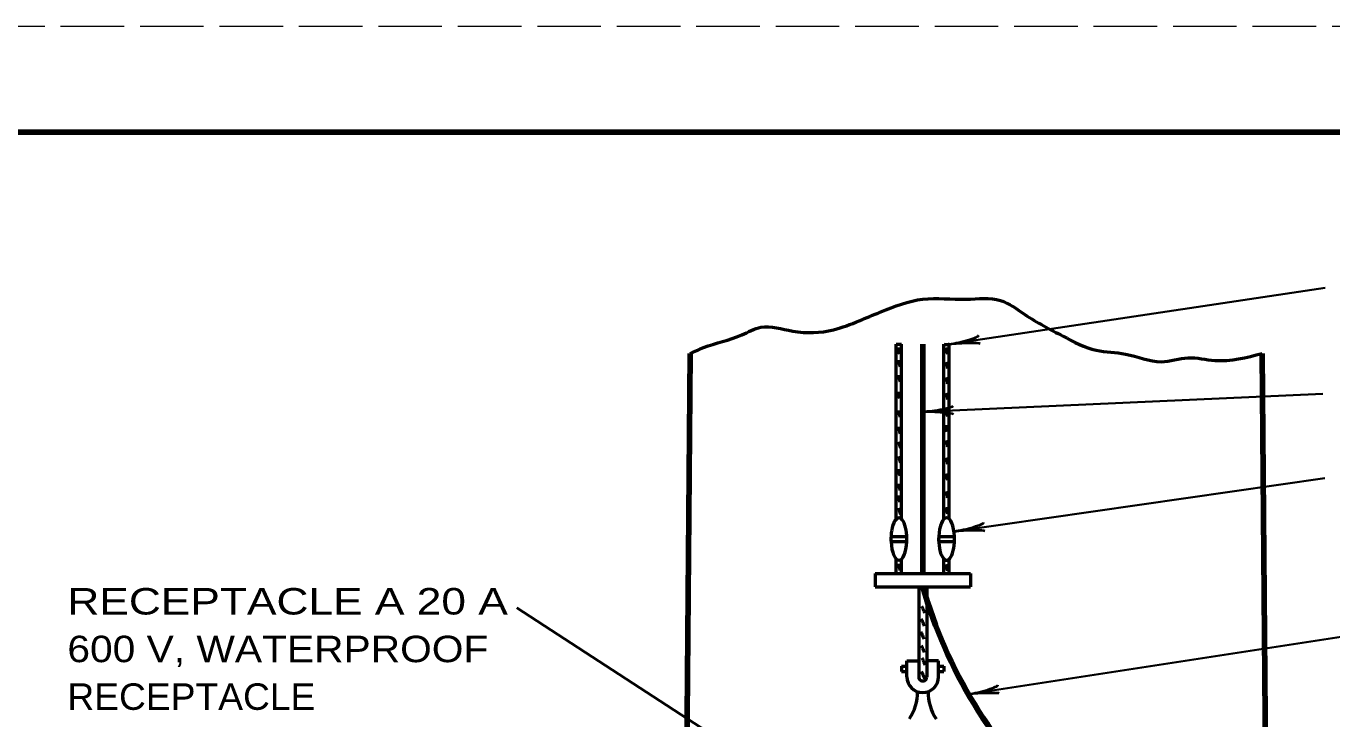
# Model space of a CAD drawing. Extents: x -1 to 679, y 0 to 440.
# Drawn here: x 332.8 to 456.1, y 374.2 to 439.6 of the extents above; entities that cross this region are included whole.
import ezdxf

# ---------------------------------------------------------------- set-up
doc = ezdxf.new("R2010")
doc.units = 0
doc.linetypes.add('LONG_DASHED', pattern=[7.5, 6, -1.5])
doc.layers.add('1', color=7, linetype='Continuous', lineweight=35)
doc.layers.add('61', color=7, linetype='Continuous', lineweight=35)

msp = doc.modelspace()

# ---------------------------------------------------------------- linework, layer by layer
at = {"layer": '1'}
for p, q in [((419.95, 409.606), (455.443, 414.94)), ((417.45, 403.246), (455.206, 404.943)), ((420.4, 391.942), (455.396, 396.984)), ((421.756, 376.569), (487.534, 386.706)), ((409.753, 364.833), (379.138, 384.739))]:
    msp.add_line(p, q, dxfattribs=at)
at = {"layer": '1', "lineweight": 53}
for p, q in [((414.95, 393.106), (414.95, 409.606)), ((415.45, 393.106), (415.45, 409.606)), ((419.45, 393.106), (419.45, 409.606)), ((419.95, 393.106), (419.95, 409.606)), ((414.456, 391.47), (415.944, 391.47)), ((415.944, 390.97), (414.456, 390.97)), ((418.956, 391.47), (420.444, 391.47)), ((420.444, 390.97), (418.956, 390.97)), ((414.95, 387.971), (414.95, 389.335)), ((415.45, 387.971), (415.45, 389.335)), ((419.45, 387.971), (419.45, 389.335)), ((419.95, 387.971), (419.95, 389.335)), ((412.95, 387.971), (421.95, 387.971)), ((412.95, 387.971), (412.95, 386.721)), ((421.95, 387.971), (421.95, 386.721)), ((412.95, 386.721), (421.95, 386.721)), ((417.075, 386.721), (417.075, 378.218)), ((417.825, 386.721), (417.825, 378.221)), ((415.95, 378.218), (415.95, 379.718)), ((415.95, 379.718), (417.075, 379.718)), ((418.95, 379.721), (417.825, 379.721)), ((418.95, 378.221), (418.95, 379.721)), ((415.45, 379.218), (415.95, 379.218)), ((415.45, 379.218), (415.45, 378.718)), ((415.45, 378.718), (415.95, 378.718)), ((418.95, 379.218), (419.45, 379.218)), ((418.95, 378.718), (419.45, 378.718)), ((419.45, 379.218), (419.45, 378.718))]:
    msp.add_line(p, q, dxfattribs=at)
at = {"layer": '1', "lineweight": 200}
msp.add_line((417.45, 387.971), (417.45, 409.606), dxfattribs=at)
at = {"layer": '1', "lineweight": 106}
for p, q in [((394.317, 267.245), (395.488, 408.744)), ((450.738, 257.745), (449.488, 408.744))]:
    msp.add_line(p, q, dxfattribs=at)
at = {"layer": '1', "lineweight": 200}
msp.add_arc((461.415, 399.379), 45.751, 196.06279, 226.51634, dxfattribs=at)
at = {"layer": '1', "lineweight": 53}
for centre, radius, start, end in [((417.45, 378.221), 1.5, 180.08989, 0), ((417.45, 378.197), 0.376, 176.82066, 3.53584), ((412.445, 376.744), 4.506, 326.28532, 0.79097), ((422.457, 376.744), 4.506, 179.20914, 213.71468)]:
    msp.add_arc(centre, radius, start, end, dxfattribs=at)
at = {"layer": '1', "lineweight": 40}
for centre, major_axis, ratio, start_param, end_param in [((420.988, 410.041), (-1.743, -0.42), 0.122415, 0.8963533, 3.1415927), ((420.988, 410.041), (-1.743, -0.42), 0.122415, 0.8963533, 3.1415927), ((421.09, 409.563), (1.763, 0.087), 0.07063, 6.2823074, 8.5597026), ((421.09, 409.563), (1.763, 0.087), 0.07063, 6.2823074, 8.5597026), ((418.528, 403.572), (-1.777, -0.236), 0.122415, 0.8963533, 3.1415927), ((418.528, 403.572), (-1.777, -0.236), 0.122415, 0.8963533, 3.1415927), ((418.579, 403.085), (1.763, -0.097), 0.07063, 6.2823074, 8.5597026), ((418.579, 403.085), (1.763, -0.097), 0.07063, 6.2823074, 8.5597026), ((421.44, 392.371), (-1.745, -0.409), 0.122415, 0.8963533, 3.1415927), ((421.44, 392.371), (-1.745, -0.409), 0.122415, 0.8963533, 3.1415927), ((421.539, 391.892), (1.764, 0.077), 0.07063, 6.2823074, 8.5597026), ((421.539, 391.892), (1.764, 0.077), 0.07063, 6.2823074, 8.5597026), ((422.792, 377.008), (-1.741, -0.426), 0.122415, 0.8963533, 3.1415927), ((422.792, 377.008), (-1.741, -0.426), 0.122415, 0.8963533, 3.1415927), ((422.896, 376.531), (-1.763, -0.094), 0.07063, 3.1407148, 5.41811), ((422.896, 376.531), (-1.763, -0.094), 0.07063, 3.1407148, 5.41811)]:
    msp.add_ellipse(centre, major_axis=major_axis, ratio=ratio, start_param=start_param, end_param=end_param, dxfattribs=at)
at = {"layer": '1', "lineweight": 53}
for centre, start_param, end_param in [((415.2, 391.22), 1.4454628, 4.8377225), ((419.7, 391.22), 1.6961242, 4.5870612), ((415.2, 391.22), 4.5870612, 4.8377168), ((415.2, 391.22), 4.8377168, 7.7286538), ((415.2, 391.22), 1.4454685, 1.6961242), ((419.7, 391.22), 4.5870554, 7.9793152), ((419.7, 391.22), 4.5870612, 4.8377168), ((419.7, 391.22), 1.4454685, 1.6961242)]:
    msp.add_ellipse(centre, major_axis=(0, -2), ratio=0.375, start_param=start_param, end_param=end_param, dxfattribs=at)
for points in [[(395.488, 408.744), (396.751, 409.29), (400.362, 410.494), (402.168, 411.216), (405.177, 410.855), (409.029, 410.975), (411.437, 411.818), (413.483, 412.661), (417.456, 413.865), (421.548, 413.865), (424.799, 413.745), (427.086, 412.42), (430.697, 410.373), (433.827, 409.049), (436.596, 408.688), (439.966, 407.965), (442.494, 408.326), (445.022, 408.085), (449.488, 408.744)], [(414.95, 409.606), (415.085, 409.631), (415.251, 409.609), (415.372, 409.616), (415.45, 409.606)], [(415.123, 409.298), (415.15, 409.079), (415.26, 408.696)], [(419.45, 409.606), (419.594, 409.578), (419.745, 409.586), (419.836, 409.601), (419.95, 409.606)], [(419.636, 409.298), (419.664, 409.079), (419.773, 408.696)], [(415.178, 408.121), (415.205, 407.902), (415.315, 407.519)], [(419.664, 407.957), (419.691, 407.738), (419.8, 407.355)], [(415.178, 406.698), (415.205, 406.48), (415.315, 406.096)], [(419.664, 406.507), (419.691, 406.288), (419.8, 405.905)], [(415.123, 405.111), (415.15, 404.893), (415.26, 404.51)], [(419.664, 405.029), (419.691, 404.81), (419.8, 404.427)], [(415.178, 403.36), (415.205, 403.141), (415.315, 402.758)], [(419.636, 403.415), (419.664, 403.196), (419.773, 402.813)], [(415.178, 401.801), (415.205, 401.582), (415.315, 401.199)], [(419.582, 401.965), (419.609, 401.746), (419.719, 401.363)], [(419.664, 400.569), (419.691, 400.35), (419.8, 399.967)], [(415.205, 400.432), (415.232, 400.214), (415.342, 399.83)], [(415.205, 399.037), (415.232, 398.818), (415.342, 398.435)], [(419.664, 398.928), (419.691, 398.709), (419.8, 398.326)], [(415.15, 397.806), (415.178, 397.587), (415.287, 397.204)], [(419.636, 397.423), (419.664, 397.204), (419.773, 396.821)], [(415.178, 396.438), (415.205, 396.219), (415.315, 395.836)], [(419.664, 395.753), (419.691, 395.535), (419.8, 395.152)], [(415.15, 395.343), (415.178, 395.124), (415.287, 394.741)], [(415.205, 394.166), (415.232, 393.948), (415.342, 393.565)], [(419.636, 394.221), (419.664, 394.002), (419.773, 393.619)], [(415.178, 388.886), (415.205, 388.667), (415.315, 388.284)], [(419.636, 388.858), (419.664, 388.639), (419.773, 388.256)], [(417.34, 384.892), (417.525, 384.459), (417.618, 384.211)], [(417.309, 383.686), (417.494, 383.253), (417.587, 383.006)], [(417.278, 382.449), (417.464, 382.017), (417.556, 381.769)], [(417.309, 381.182), (417.494, 380.749), (417.587, 380.502)], [(417.371, 380.007), (417.556, 379.575), (417.649, 379.327)], [(417.34, 378.709), (417.525, 378.276), (417.618, 378.029)]]:
    msp.add_spline(points, degree=3, dxfattribs=at)
at = {"layer": '61', "linetype": 'LONG_DASHED', "lineweight": 13}
msp.add_line((-1.425, 439.645), (678.595, 439.645), dxfattribs=at)
at = {"layer": '61', "lineweight": 158}
msp.add_lwpolyline([(667.615, 429.645), (28.575, 429.645), (28.575, 9.625)], dxfattribs=at)

# ---------------------------------------------------------------- texts
at = {"layer": '1'}
for s, width, p in [('RECEPTACLE A 20 A', 1.25, (336.716, 384.096)), ('600 V, WATERPROOF', 1.15, (336.716, 379.596)), ('RECEPTACLE', 1.05, (336.716, 375.096))]:
    msp.add_text(s, height=2.5, dxfattribs=dict(at, width=width)).set_placement(p)

doc.saveas('drawing.dxf')
